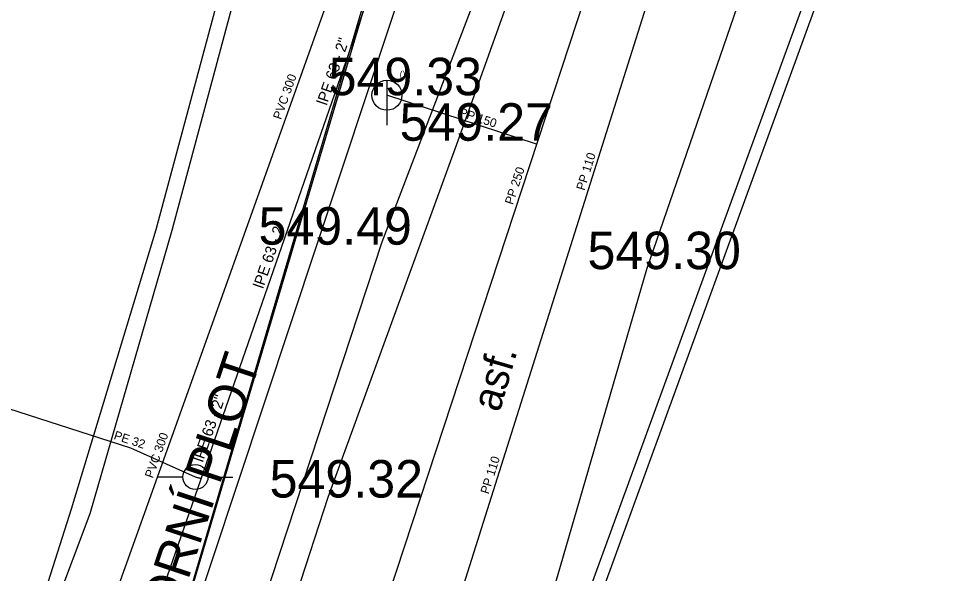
# Model space of a CAD drawing. Extents: x -669995 to -669686, y -1125551 to -1125263.
# Drawn here: x -669850.82 to -669832.03, y -1125398.12 to -1125387.03 of the extents above; entities that cross this region are included whole.
import ezdxf

# ---------------------------------------------------------------- set-up
doc = ezdxf.new("R2010")
doc.units = 0
for name, color, linetype in [('G_Bod_tecka', 7, 'Continuous'), ('G_Bod_vyska', 7, 'Continuous'), ('G_Plochy_zpevnene', 7, 'Continuous'), ('G_Ploty', 7, 'Continuous'), ('G_Popisy_povrchu', 7, 'Continuous'), ('G_Poznamky_odkaz', 7, 'Continuous'), ('G_Site-kanalizace', 7, 'Continuous'), ('G_Site-vodovod', 7, 'Continuous'), ('G_Z_ELsilove_nadz_kotovane', 7, 'Continuous'), ('G_Z_ELsilove_podz_kotovane', 7, 'Continuous'), ('G_Z_ELsilove_zrusene', 7, 'Continuous'), ('G_Z_KANAL_podz_kotovane', 7, 'Continuous'), ('G_Z_KANAL_podz_priblizne', 7, 'Continuous'), ('G_Z_PLYNY_podz_geodeticky', 7, 'Continuous'), ('G_Z_VODA_podz_kotovane', 7, 'Continuous'), ('Vrstva 11', 7, 'Continuous'), ('Vrstva 17', 7, 'Continuous'), ('Vrstva 2', 7, 'Continuous'), ('Vrstva 21', 7, 'Continuous'), ('Vrstva 26', 7, 'Continuous'), ('Vrstva 3', 7, 'Continuous'), ('Vrstva 4', 7, 'Continuous'), ('Vrstva 5', 7, 'Continuous'), ('Vrstva 6', 7, 'Continuous'), ('Vrstva 8', 7, 'Continuous')]:
    doc.layers.add(name, color=color, linetype=linetype)

msp = doc.modelspace()

# ---------------------------------------------------------------- linework, layer by layer
at = {"layer": 'G_Bod_tecka'}
for p, q in [((-669843.46, -1125388.56), (-669843.46, -1125388.56)), ((-669842.04, -1125389.47), (-669842.04, -1125389.47)), ((-669844.86, -1125391.55), (-669844.86, -1125391.55)), ((-669838.26, -1125392.04), (-669838.26, -1125392.04)), ((-669844.64, -1125396.61), (-669844.64, -1125396.61))]:
    msp.add_line(p, q, dxfattribs=at)
at = {"layer": 'G_Plochy_zpevnene'}
for p, q in [((-669838.26, -1125392.04), (-669834.25, -1125380.38)), ((-669839.7, -1125382.92), (-669842.04, -1125389.47)), ((-669842.04, -1125389.47), (-669844.64, -1125396.61)), ((-669840.69, -1125400.39), (-669838.26, -1125392.04)), ((-669844.64, -1125396.61), (-669846.35, -1125401.86))]:
    msp.add_line(p, q, dxfattribs=at)
at = {"layer": 'G_Ploty'}
for p, q in [((-669840.18, -1125400.57), (-669835.04, -1125386.48)), ((-669839.81, -1125400.29), (-669834.84, -1125386.66))]:
    msp.add_line(p, q, dxfattribs=at)
for points in [[(-669838.42, -1125372.24), (-669842.38, -1125384.06), (-669844.86, -1125391.55)], [(-669844.86, -1125391.55), (-669850.65, -1125408.99)]]:
    msp.add_lwpolyline(points, dxfattribs=at)
at = {"layer": 'G_Site-kanalizace'}
msp.add_line((-669843.46, -1125388.26), (-669843.46, -1125389.16), dxfattribs=at)
msp.add_circle((-669843.46, -1125388.56), 0.3, dxfattribs=at)
at = {"layer": 'G_Site-vodovod'}
for p, q in [((-669847.54, -1125396.2), (-669848.04, -1125396.2)), ((-669847.04, -1125396.2), (-669846.54, -1125396.2))]:
    msp.add_line(p, q, dxfattribs=at)
msp.add_circle((-669847.29, -1125396.2), 0.25, dxfattribs=at)
at = {"layer": 'G_Z_ELsilove_nadz_kotovane'}
msp.add_lwpolyline([(-669849.93, -1125407.07), (-669848.469, -1125402.12), (-669848.385, -1125401.833), (-669837.47, -1125364.84), (-669822.83, -1125326.67)], dxfattribs=at)
at = {"layer": 'G_Z_ELsilove_podz_kotovane'}
msp.add_lwpolyline([(-669793.678, -1125277.309), (-669806.73, -1125294.49), (-669822.69, -1125326.67), (-669837.43, -1125364.93), (-669849.93, -1125407.07), (-669860.28, -1125448.68)], dxfattribs=at)
at = {"layer": 'G_Z_ELsilove_zrusene'}
for points in [[(-669814.133, -1125400.288), (-669817.058, -1125400.535), (-669822.208, -1125400.969), (-669822.216, -1125400.97), (-669830.092, -1125401.691), (-669830.468, -1125401.725), (-669836.547, -1125402.21), (-669836.999, -1125402.329), (-669839.381, -1125402.956), (-669840.894, -1125403.26), (-669842.624, -1125403.184), (-669845.992, -1125402.648), (-669847.235, -1125402.45), (-669848.469, -1125402.12), (-669850.471, -1125401.585), (-669850.931, -1125400.913), (-669850.742, -1125399.899), (-669849.768, -1125396.834), (-669848.073, -1125391.245), (-669846.736, -1125386.251)], [(-669814.133, -1125400.288), (-669817.058, -1125400.535), (-669822.208, -1125400.969), (-669822.216, -1125400.97), (-669830.092, -1125401.691), (-669830.468, -1125401.725), (-669836.547, -1125402.21), (-669836.999, -1125402.329), (-669839.381, -1125402.956), (-669840.894, -1125403.26), (-669842.624, -1125403.184), (-669845.992, -1125402.648), (-669847.235, -1125402.45), (-669848.469, -1125402.12), (-669850.471, -1125401.585), (-669850.931, -1125400.913), (-669850.742, -1125399.899), (-669849.768, -1125396.834), (-669848.073, -1125391.245), (-669846.736, -1125386.251)], [(-669846.446, -1125386.365), (-669847.762, -1125391.264), (-669849.405, -1125396.935), (-669850.481, -1125399.811), (-669850.655, -1125400.859), (-669850.17, -1125401.432), (-669848.385, -1125401.833), (-669847.104, -1125402.12), (-669843.782, -1125402.515), (-669842.45, -1125402.673), (-669840.932, -1125402.788), (-669839.388, -1125402.551), (-669838.345, -1125402.306), (-669836.654, -1125401.909), (-669830.57, -1125401.283), (-669823.718, -1125400.709), (-669822.529, -1125400.61)], [(-669846.446, -1125386.365), (-669847.762, -1125391.264), (-669849.405, -1125396.935), (-669850.481, -1125399.811), (-669850.655, -1125400.859), (-669850.17, -1125401.432), (-669848.385, -1125401.833), (-669847.104, -1125402.12), (-669843.782, -1125402.515), (-669842.45, -1125402.673), (-669840.932, -1125402.788), (-669839.388, -1125402.551), (-669838.345, -1125402.306), (-669836.654, -1125401.909), (-669830.57, -1125401.283), (-669823.718, -1125400.709), (-669822.529, -1125400.61)]]:
    msp.add_lwpolyline(points, dxfattribs=at)
at = {"layer": 'G_Z_KANAL_podz_kotovane'}
msp.add_line((-669834.34, -1125370.92), (-669844.67, -1125402.32), dxfattribs=at)
for points in [[(-669837.47, -1125406.42), (-669844.1, -1125405.26), (-669833.36, -1125371.21), (-669821.31, -1125332.23), (-669811.44, -1125307.86), (-669795.39, -1125283.71), (-669791, -1125278.72), (-669790.199, -1125277.833)], [(-669840.47, -1125389.54), (-669840.47, -1125389.54), (-669843.46, -1125388.56)]]:
    msp.add_lwpolyline(points, dxfattribs=at)
at = {"layer": 'G_Z_KANAL_podz_priblizne'}
msp.add_lwpolyline([(-669859.5, -1125451.55), (-669856.48, -1125430.45), (-669853.73, -1125415.63), (-669852.14, -1125407.38), (-669851.85, -1125406.81), (-669846.78, -1125392.66), (-669840.64, -1125375.45), (-669843.45, -1125370.23)], dxfattribs=at)
at = {"layer": 'G_Z_PLYNY_podz_geodeticky'}
msp.add_lwpolyline([(-669839.68, -1125381.34), (-669843.56, -1125391.5), (-669845.77, -1125398.22), (-669846.85, -1125401.64), (-669847.2, -1125402.75), (-669848.28, -1125405.76), (-669848.45, -1125406.31), (-669848.51, -1125406.54), (-669849.81, -1125412.17), (-669852.19, -1125424.43), (-669853.31, -1125431.05), (-669856.64, -1125450), (-669860.14, -1125455.63), (-669860.74, -1125456.58)], dxfattribs=at)
at = {"layer": 'G_Z_VODA_podz_kotovane'}
for points in [[(-669858.63, -1125450.57), (-669858.25, -1125448.42), (-669857.85, -1125445.05), (-669856.38, -1125434.43), (-669854.37, -1125424.91), (-669851.09, -1125407.69), (-669849.25, -1125402.21), (-669840.03, -1125375.63), (-669840.08, -1125374.27), (-669839.76, -1125372.61), (-669839.5, -1125370.59), (-669837.98, -1125365.03), (-669838.35, -1125363.15), (-669838.04, -1125362.68), (-669836.94, -1125362.97)], [(-669847.18, -1125396.23), (-669847.29, -1125396.2), (-669848.58, -1125395.62), (-669852.66, -1125394.31), (-669853.8, -1125393.77)]]:
    msp.add_lwpolyline(points, dxfattribs=at)
at = {"layer": 'Vrstva 11'}
msp.add_line((-669834.34, -1125370.92), (-669844.67, -1125402.32), dxfattribs=at)
msp.add_lwpolyline([(-669840.466, -1125389.541), (-669840.47, -1125389.54), (-669843.46, -1125388.56)], dxfattribs=at)
at = {"layer": 'Vrstva 17'}
msp.add_lwpolyline([(-669859.5, -1125451.55), (-669856.48, -1125430.45), (-669853.73, -1125415.63), (-669852.14, -1125407.38), (-669851.85, -1125406.81), (-669846.78, -1125392.66), (-669840.64, -1125375.45), (-669843.45, -1125370.23)], dxfattribs=at)
at = {"layer": 'Vrstva 21'}
msp.add_lwpolyline([(-669837.47, -1125406.42), (-669844.1, -1125405.26), (-669833.36, -1125371.21), (-669821.31, -1125332.23), (-669811.44, -1125307.86), (-669795.39, -1125283.71), (-669791, -1125278.72), (-669790.199, -1125277.833)], dxfattribs=at)
at = {"layer": 'Vrstva 26'}
for points in [[(-669858.63, -1125450.57), (-669858.245, -1125448.421), (-669857.85, -1125445.05), (-669856.38, -1125434.43), (-669854.37, -1125424.91), (-669851.09, -1125407.69), (-669849.25, -1125402.21), (-669840.03, -1125375.63), (-669840.08, -1125374.27), (-669839.76, -1125372.61), (-669839.5, -1125370.59), (-669837.98, -1125365.03), (-669838.35, -1125363.15), (-669838.04, -1125362.68), (-669836.94, -1125362.97)], [(-669847.177, -1125396.233), (-669847.29, -1125396.2), (-669848.58, -1125395.62), (-669852.66, -1125394.31), (-669853.801, -1125393.766)]]:
    msp.add_lwpolyline(points, dxfattribs=at)
at = {"layer": 'Vrstva 5'}
msp.add_line((-669837.43, -1125364.93), (-669849.93, -1125407.07), dxfattribs=at)
at = {"layer": 'Vrstva 6'}
msp.add_line((-669847.29, -1125396.2), (-669847.29, -1125396.2), dxfattribs=at)
at = {"layer": 'Vrstva 8'}
msp.add_line((-669843.46, -1125388.56), (-669843.46, -1125388.56), dxfattribs=at)

# ---------------------------------------------------------------- texts
at = {"layer": 'G_Bod_vyska'}
for s, p in [('549.33', (-669844.626, -1125388.56)), ('549.27', (-669843.206, -1125389.47)), ('549.49', (-669846.028, -1125391.55)), ('549.30', (-669839.448, -1125392.04)), ('549.32', (-669845.806, -1125396.61))]:
    msp.add_text(s, height=0.75, dxfattribs=at).set_placement(p)
at = {"layer": 'G_Popisy_povrchu'}
msp.add_text('asf.', height=0.6, rotation=73.7771, dxfattribs=at).set_placement((-669841.208, -1125394.921))
at = {"layer": 'G_Poznamky_odkaz'}
msp.add_text('PROVIZORNÍ PLOT', height=0.75, rotation=71.6373, dxfattribs=at).set_placement((-669848.86, -1125402.558))
at = {"layer": 'Vrstva 2'}
msp.add_text('\xa0()', height=0.1316, dxfattribs=at).set_placement((-669843.255, -1125388.207))
at = {"layer": 'Vrstva 3'}
for s, rotation, p in [('PVC 300', 70.3393, (-669845.579, -1125389.059)), ('PP 150', 341.8126, (-669842.03, -1125388.973)), ('PP 110', 72.5158, (-669839.511, -1125390.477)), ('PP 250', 71.8126, (-669840.941, -1125390.762)), ('PVC 300', 70.3279, (-669848.144, -1125396.235)), ('PP 110', 72.5427, (-669841.428, -1125396.552))]:
    msp.add_text(s, height=0.1755, rotation=rotation, dxfattribs=at).set_placement(p)
at = {"layer": 'Vrstva 4'}
for s, height, rotation, p in [('lPE 63 - 2"', 0.21938, 71.0033, (-669844.665, -1125388.776)), ('lPE 63 - 2"', 0.21938, 70.8846, (-669845.937, -1125392.443)), ('lPE 63 - 2"', 0.21938, 70.8776, (-669847.142, -1125395.917)), ('PE 32', 0.1755, 341.8021, (-669848.937, -1125395.437))]:
    msp.add_text(s, height=height, rotation=rotation, dxfattribs=at).set_placement(p)

doc.saveas('drawing.dxf')
